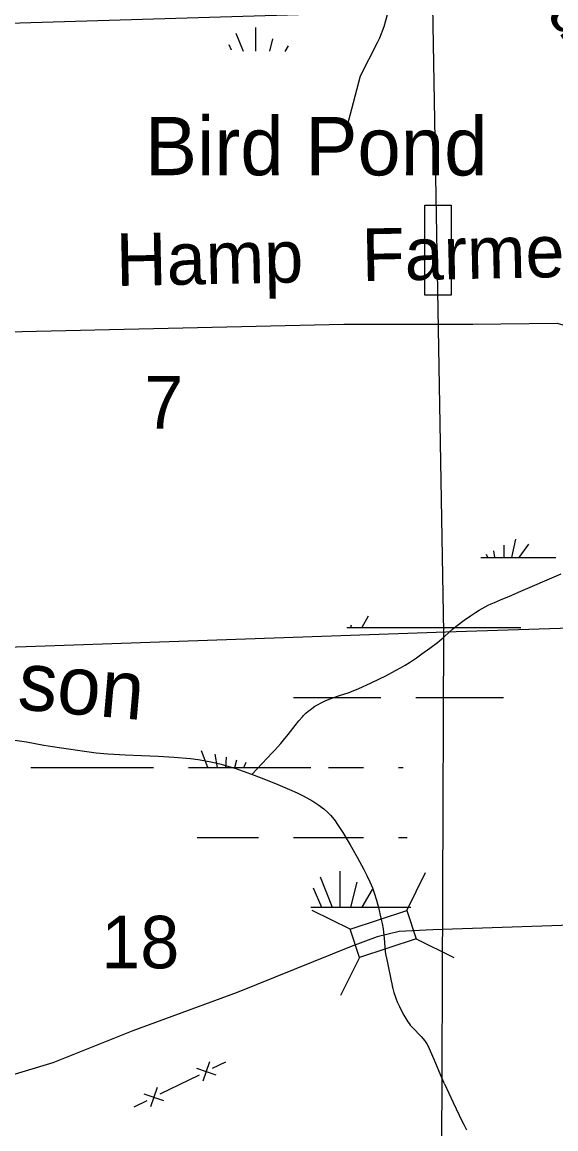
# Model space of a CAD drawing. Extents: x 2480962 to 2688785, y 277103 to 599240.
# Drawn here: x 2550816 to 2555391, y 481870 to 491360 of the extents above; entities that cross this region are included whole.
import ezdxf

# ---------------------------------------------------------------- set-up
doc = ezdxf.new("R2010")
doc.units = 0
for name, color, linetype in [('Bridges', 7, 'Continuous'), ('County Routes Highway Center Lines', 7, 'Continuous'), ('Lakes and Ponds Text', 7, 'Continuous'), ('Level 31', 7, 'Continuous'), ('Local Roads Paved', 7, 'Continuous'), ('Local Roads Related Text', 7, 'Continuous'), ('Narrow River Creek and Branch and Slough', 7, 'Continuous'), ('Section Lines', 7, 'Continuous'), ('Section Numbers', 7, 'Continuous'), ('Swamps', 7, 'Continuous'), ('Uninventoried Roads and Features', 7, 'Continuous')]:
    doc.layers.add(name, color=color, linetype=linetype)

msp = doc.modelspace()

# ---------------------------------------------------------------- linework, layer by layer
at = {"layer": 'Bridges'}
for p, q in [((2554112.49, 483742.973), (2554274.337, 484066.821)), ((2553626.795, 483580.971), (2553302.947, 483742.818)), ((2554193.491, 483500.125), (2554517.339, 483338.279)), ((2553707.796, 483338.124), (2553545.949, 483014.276))]:
    msp.add_line(p, q, dxfattribs=at)
msp.add_lwpolyline([(2553626.795, 483580.971), (2554112.49, 483742.973), (2554193.491, 483500.125), (2553707.796, 483338.124)], close=True, dxfattribs=at)
at = {"layer": 'County Routes Highway Center Lines'}
msp.add_lwpolyline([(2555865.39, 483627.896), (2554337.258, 483575.716), (2554046.54, 483560.807), (2553860.183, 483516.082), (2553636.554, 483434.084), (2552660.04, 483039.006), (2551765.524, 482711.017), (2551079.728, 482435.208), (2550602.653, 482293.576), (2550490.839, 482286.122), (2549171.427, 482301.031), (2548321.637, 482323.393), (2547874.379, 482368.119), (2546957.5, 482509.751), (2545906.443, 482658.837), (2544721.21, 482830.286), (2543066.355, 483053.915), (2542402.922, 483128.458), (2541992.935, 483165.729), (2541620.22, 483158.275), (2540718.25, 483098.641), (2539875.914, 483031.552), (2538578.865, 483009.189), (2536029.494, 482957.009)], dxfattribs=at)
at = {"layer": 'Level 31'}
msp.add_lwpolyline([(2554267.777, 489789.693), (2554493.082, 489789.693), (2554493.082, 489019.564), (2554267.777, 489019.564)], close=True, dxfattribs=at)
at = {"layer": 'Local Roads Paved'}
msp.add_lwpolyline([(2546579.793, 489678.694), (2547386.025, 489866.19), (2547723.518, 489931.814), (2548276.631, 489941.189), (2548726.621, 489931.814), (2549026.615, 489866.19), (2549532.854, 489584.947), (2549851.597, 489463.074), (2550001.594, 489416.2), (2550507.833, 488909.961), (2550685.954, 488703.716), (2553573.392, 488769.339), (2554679.618, 488769.339), (2555401.477, 488778.714), (2555626.473, 488713.09), (2555804.594, 488628.717), (2556226.46, 488731.84), (2556751.448, 488891.211), (2557107.691, 488928.711), (2557567.056, 489106.832), (2557867.049, 489247.454), (2558879.527, 490016.187)], dxfattribs=at)
at = {"layer": 'Narrow River Creek and Branch and Slough'}
for points in [[(2552786.179, 484909.938), (2552873.311, 485001.399), (2552959.525, 485093.737), (2552977.873, 485113.674), (2553005.081, 485143.862), (2553032.162, 485174.149), (2553056.337, 485202.098), (2553096.783, 485252.442), (2553156.086, 485329.249), (2553186.585, 485367.223), (2553218.55, 485404.287), (2553228.709, 485415.163), (2553248.634, 485434.574), (2553266.936, 485450.551), (2553283.559, 485463.792), (2553298.528, 485474.837), (2553325.588, 485493.004), (2553346.516, 485505.71), (2553378.758, 485523.393), (2553411.806, 485539.549), (2553447.328, 485554.79), (2553478.872, 485566.712), (2553534.707, 485585.558), (2553618.636, 485612.81), (2553660.04, 485627.791), (2553680.475, 485635.986), (2553700.681, 485644.79), (2553802.065, 485691.403), (2553877.603, 485727.377), (2553933.801, 485755.332), (2554017.109, 485799.436), (2554058.22, 485822.697), (2554098.906, 485846.906), (2554134.972, 485869.424), (2554196.865, 485910.254), (2554242.404, 485941.956), (2554309.572, 485991.031), (2554375.717, 486041.658), (2554395.782, 486057.866), (2554429.845, 486087.408), (2554480.111, 486132.696), (2554505.666, 486154.904), (2554531.995, 486176.283), (2554604.174, 486230.949), (2554659.506, 486270.215), (2554701.904, 486298.208), (2554734.303, 486318.18), (2554784.008, 486346.193), (2554809.413, 486359.207), (2554835.22, 486371.489), (2554864.517, 486384.545), (2554916.173, 486406.31), (2554994.003, 486437.885), (2555032.802, 486453.913), (2555071.355, 486470.545), (2555435.506, 486630.007)], [(2550754.171, 485203.579), (2550853.963, 485187.885), (2551002.668, 485161.281), (2551077.009, 485148.285), (2551151.608, 485136.529), (2551349.825, 485107.903), (2551449.15, 485095.322), (2551548.78, 485085.307), (2551602.905, 485081.37), (2551697.737, 485076.759), (2551840.107, 485072.351), (2551911.279, 485069.881), (2551982.402, 485066.377), (2552120.047, 485056.927), (2552257.543, 485044.721), (2552324.413, 485036.696), (2552374.291, 485028.925), (2552448.678, 485014.43), (2552522.56, 484996.504), (2552588.612, 484977.677), (2552637.587, 484962.296), (2552710.434, 484937.558), (2552782.91, 484911.264), (2552864.782, 484879.983), (2552986.405, 484830.795), (2553107.445, 484779.63), (2553172.093, 484750.65), (2553219.667, 484727.386), (2553254.854, 484708.888), (2553306.874, 484679.168), (2553358.023, 484646.725), (2553381.995, 484629.69), (2553402.049, 484613.805), (2553435.108, 484583.936), (2553458.236, 484559.923), (2553474.662, 484541.071), (2553497.848, 484511.537), (2553519.324, 484480.619), (2553563.68, 484411.056), (2553627.104, 484305.659), (2553687.847, 484198.531), (2553744.597, 484095.132), (2553771.66, 484042.785), (2553797.025, 483989.309), (2553819.018, 483935.454), (2553833.36, 483894.411), (2553852.333, 483832.017), (2553869.402, 483768.897), (2553891.665, 483677.281), (2553901.239, 483631.222), (2553909.464, 483584.873), (2553913.438, 483555.989), (2553918.125, 483505.14), (2553923.862, 483428.736), (2553928.107, 483390.754), (2553934.472, 483353.093), (2553935.602, 483347.615), (2553989.949, 483083.48)], [(2553988.623, 483090.602), (2553989.354, 483086.526), (2553989.949, 483083.48), (2553990.917, 483078.923), (2553991.97, 483074.374), (2554001.775, 483038.391), (2554011.98, 483007.468), (2554022.026, 482980.803), (2554031.586, 482957.749), (2554049.833, 482917.97), (2554064.596, 482888.557), (2554088.101, 482845.01), (2554112.771, 482802.021), (2554122.494, 482786.631), (2554132.421, 482772.786), (2554142.333, 482760.244), (2554162.16, 482737.643), (2554236.002, 482662.183), (2554253.381, 482642.719), (2554265.601, 482627.599), (2554274.188, 482615.881), (2554285.958, 482597.576), (2554296.173, 482578.242), (2554314.217, 482538.695), (2554344.208, 482468.754), (2554387.834, 482363.217), (2554410.19, 482310.7), (2554433.616, 482258.678), (2554433.752, 482258.387), (2554433.891, 482258.097)], [(2554436.229, 482256.586), (2554511.612, 482095.348), (2554586.995, 481934.11), (2554600.682, 481906.596), (2554613.624, 481883.054), (2554625.571, 481862.797)]]:
    msp.add_lwpolyline(points, dxfattribs=at)
at = {"layer": 'Section Lines'}
for p, q in [((2554333.809, 491497.773), (2554426.487, 486126.849)), ((2549056.185, 491302.217), (2554334.448, 491460.787)), ((2559675.987, 486300.998), (2554446.492, 486127.538)), ((2554446.492, 486127.538), (2549120.782, 485943.983)), ((2554426.487, 486126.849), (2554408.881, 480853.998))]:
    msp.add_line(p, q, dxfattribs=at)
msp.add_lwpolyline([(2553600.239, 486169.545), (2554640.618, 486169.561)], dxfattribs=at)
at = {"layer": 'Swamps'}
for p, q in [((2555076.068, 486769.068), (2555159.845, 486882.77)), ((2554640.618, 486169.561), (2555090.617, 486169.568)), ((2553140.63, 485569.539), (2553890.628, 485569.551)), ((2554190.627, 485569.556), (2554640.626, 485569.563)), ((2554640.626, 485569.563), (2554940.625, 485569.568)), ((2550890.643, 484969.504), (2551940.641, 484969.521)), ((2552240.64, 484969.526), (2553290.637, 484969.543)), ((2553440.637, 484969.545), (2553740.636, 484969.55)), ((2553140.646, 484369.542), (2553740.644, 484369.552)), ((2553370.157, 484032.222), (2553473.178, 483769.549)), ((2553539.308, 484080.553), (2553539.312, 483769.55)), ((2553309.747, 483935.563), (2553380.56, 483769.547)), ((2553684.295, 483983.898), (2553630.686, 483769.45)), ((2553817.201, 483923.489), (2553727.483, 483769.682))]:
    msp.add_line(p, q, dxfattribs=at)
for points in [[(2552817.324, 491314.009), (2552817.327, 491109.88)], [(2552648.173, 491265.678), (2552709.209, 491110.053)], [(2552962.312, 491217.354), (2552935.397, 491109.69)], [(2552587.764, 491169.019), (2552607.637, 491122.426)], [(2553095.218, 491156.945), (2553067.528, 491109.478)], [(2554946.773, 486769.583), (2554948.745, 486874.179)], [(2555013.872, 486769.375), (2555046.328, 486925.169)], [(2554748.531, 486769.561), (2555390.608, 486769.571)], [(2554806.289, 486770.549), (2554796.985, 486794.88)], [(2554868.611, 486769.627), (2554859.593, 486827.595)], [(2553635.252, 486187.839), (2553630.654, 486169.444)], [(2553783.114, 486265.101), (2553727.451, 486169.676)], [(2552406.074, 484969.7), (2552351.696, 485112.442)], [(2552491.148, 484969.612), (2552470.765, 485081.712)], [(2552562.148, 484969.563), (2552566.91, 485056.898)], [(2552638.834, 484969.742), (2552657.085, 485033.624)], [(2552715.43, 484969.666), (2552735.144, 485013.478)], [(2554040.635, 484969.555), (2554082.13, 484969.555)], [(2552316.722, 484369.529), (2552840.646, 484369.537)], [(2554040.643, 484369.556), (2554114.752, 484369.558)], [(2553290.653, 483769.546), (2554147.375, 483769.56)]]:
    msp.add_lwpolyline(points, dxfattribs=at)
at = {"layer": 'Uninventoried Roads and Features'}
for p, q in [((2553858.617, 491182.448), (2553713.254, 490896.367)), ((2553713.254, 490896.367), (2553610.521, 490505.431)), ((2552308.815, 482390.333), (2552476.044, 482333.024)), ((2552421.085, 482445.293), (2552363.775, 482278.064)), ((2552448.564, 482389.158), (2552560.834, 482444.118)), ((2551999.487, 482169.319), (2552336.295, 482334.198)), ((2551972.007, 482225.454), (2551914.697, 482058.224)), ((2551774.948, 482059.399), (2551887.217, 482114.359)), ((2551859.737, 482170.494), (2552026.967, 482113.184))]:
    msp.add_line(p, q, dxfattribs=at)
msp.add_lwpolyline([(2553967.792, 491630.644), (2553961.462, 491525.466), (2553944.172, 491421.527), (2553916.113, 491319.964), (2553877.59, 491221.89), (2553858.617, 491182.448)], dxfattribs=at)

# ---------------------------------------------------------------- texts
at = {"layer": 'Lakes and Ponds Text'}
for s, rotation, p in [('Bird Pond', 359.9502167, (2551868.498, 490047.659)), ('inson', 354.9718389, (2550248.844, 485515.113))]:
    msp.add_text(s, height=500, rotation=rotation, dxfattribs=at).set_placement(p)
at = {"layer": 'Local Roads Related Text'}
for s, rotation, p in [('Road', 302.6120639, (2554702.478, 492382.946)), ('Hamp   Farmer', 1.1543583, (2551623.961, 489096.919))]:
    msp.add_text(s, height=450, rotation=rotation, dxfattribs=at).set_placement(p)
at = {"layer": 'Section Numbers'}
for s, rotation, p in [('7', 359.9794083, (2551862.678, 487875.014)), ('18', 359.9794167, (2551493.421, 483246.626))]:
    msp.add_text(s, height=450, rotation=rotation, dxfattribs=at).set_placement(p)

doc.saveas('drawing.dxf')
